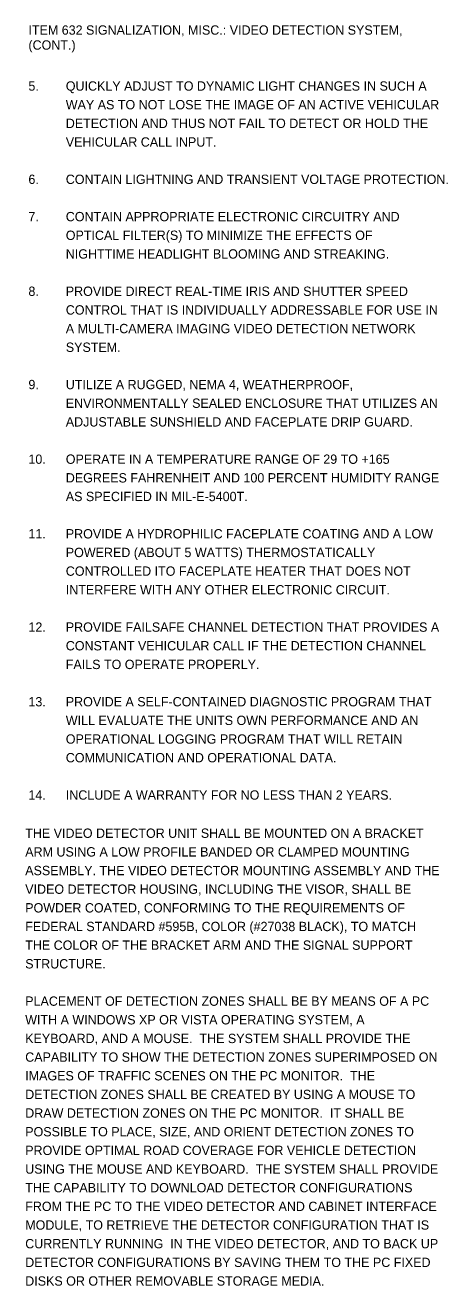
# Model space of a CAD drawing. Extents: x -39 to 75, y -25 to 14.
# Drawn here: x 53.38 to 59.71, y -23.32 to -4.4 of the extents above; entities that cross this region are included whole.
import ezdxf

# ---------------------------------------------------------------- set-up
doc = ezdxf.new("R2010")
doc.units = 0
for name, color, linetype in [('Default', 7, 'Continuous'), ('SH_Data', 7, 'Continuous'), ('SH_Text', 7, 'Continuous')]:
    doc.layers.add(name, color=color, linetype=linetype)

# ---------------------------------------------------------------- blocks, each defined once
blk = doc.blocks.new('POINT_DISPLAY')
at = {"layer": 'Default'}
blk.add_line((0, 0), (0, 0), dxfattribs=at)

msp = doc.modelspace()

# ---------------------------------------------------------------- block references
at = {"layer": 'Default', "xscale": 3.9370000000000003, "yscale": 3.9370000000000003}
msp.add_blockref('POINT_DISPLAY', (53.743, -18.102), dxfattribs=at)

# ---------------------------------------------------------------- texts
at = {"layer": 'SH_Data'}
for s, p in [('ITEM 632 SIGNALIZATION, MISC.: VIDEO DETECTION SYSTEM, ', (53.423, -4.541)), ('(CONT.)', (53.423, -4.766))]:
    msp.add_text(s, height=0.14, rotation=360, dxfattribs=at).set_placement(p)
at = {"layer": 'SH_Text'}
for s, p in [('5.', (53.423, -5.381)), ('QUICKLY ADJUST TO DYNAMIC LIGHT CHANGES IN SUCH A ', (53.983, -5.381)), ('WAY AS TO NOT LOSE THE IMAGE OF AN ACTIVE VEHICULAR ', (53.983, -5.661)), ('DETECTION AND THUS NOT FAIL TO DETECT OR HOLD THE ', (53.983, -5.941)), ('VEHICULAR CALL INPUT.', (53.983, -6.221)), ('6.', (53.423, -6.781)), ('CONTAIN LIGHTNING AND TRANSIENT VOLTAGE PROTECTION.', (53.983, -6.781)), ('7.', (53.423, -7.341)), ('CONTAIN APPROPRIATE ELECTRONIC CIRCUITRY AND ', (53.983, -7.341)), ('OPTICAL FILTER(S) TO MINIMIZE THE EFFECTS OF ', (53.983, -7.621)), ('NIGHTTIME HEADLIGHT BLOOMING AND STREAKING.', (53.983, -7.901)), ('8.', (53.423, -8.461)), ('PROVIDE DIRECT REAL-TIME IRIS AND SHUTTER SPEED ', (53.983, -8.461)), ('CONTROL THAT IS INDIVIDUALLY ADDRESSABLE FOR USE IN ', (53.983, -8.741)), ('A MULTI-CAMERA IMAGING VIDEO DETECTION NETWORK ', (53.983, -9.021)), ('SYSTEM.', (53.983, -9.301)), ('9.', (53.423, -9.861)), ('UTILIZE A RUGGED, NEMA 4, WEATHERPROOF, ', (53.983, -9.861)), ('ENVIRONMENTALLY SEALED ENCLOSURE THAT UTILIZES AN ', (53.983, -10.141)), ('ADJUSTABLE SUNSHIELD AND FACEPLATE DRIP GUARD.', (53.983, -10.421)), ('10.', (53.423, -10.981)), ('OPERATE IN A TEMPERATURE RANGE OF 29 TO +165 ', (53.983, -10.981)), ('DEGREES FAHRENHEIT AND 100 PERCENT HUMIDITY RANGE ', (53.983, -11.261)), ('AS SPECIFIED IN MIL-E-5400T.', (53.983, -11.541)), ('11.', (53.423, -12.101)), ('PROVIDE A HYDROPHILIC FACEPLATE COATING AND A LOW ', (53.983, -12.101)), ('POWERED (ABOUT 5 WATTS) THERMOSTATICALLY ', (53.983, -12.381)), ('CONTROLLED ITO FACEPLATE HEATER THAT DOES NOT ', (53.983, -12.661)), ('INTERFERE WITH ANY OTHER ELECTRONIC CIRCUIT.', (53.983, -12.941)), ('12.', (53.423, -13.501)), ('PROVIDE FAILSAFE CHANNEL DETECTION THAT PROVIDES A ', (53.983, -13.501)), ('CONSTANT VEHICULAR CALL IF THE DETECTION CHANNEL ', (53.983, -13.781)), ('FAILS TO OPERATE PROPERLY.', (53.983, -14.061)), ('13.', (53.423, -14.621)), ('PROVIDE A SELF-CONTAINED DIAGNOSTIC PROGRAM THAT ', (53.983, -14.621)), ('WILL EVALUATE THE UNITS OWN PERFORMANCE AND AN ', (53.983, -14.901)), ('OPERATIONAL LOGGING PROGRAM THAT WILL RETAIN ', (53.983, -15.181)), ('COMMUNICATION AND OPERATIONAL DATA.', (53.983, -15.461)), ('14.', (53.423, -16.021)), ('INCLUDE A WARRANTY FOR NO LESS THAN 2 YEARS.', (53.983, -16.021)), ('THE VIDEO DETECTOR UNIT SHALL BE MOUNTED ON A BRACKET ', (53.375, -16.594)), ('ARM USING A LOW PROFILE BANDED OR CLAMPED MOUNTING ', (53.375, -16.874)), ('ASSEMBLY. THE VIDEO DETECTOR MOUNTING ASSEMBLY AND THE ', (53.375, -17.154)), ('VIDEO DETECTOR HOUSING, INCLUDING THE VISOR, SHALL BE ', (53.375, -17.434)), ('POWDER COATED, CONFORMING TO THE REQUIREMENTS OF ', (53.375, -17.714)), ('FEDERAL STANDARD #595B, COLOR (#27038 BLACK), TO MATCH ', (53.375, -17.994)), ('THE COLOR OF THE BRACKET ARM AND THE SIGNAL SUPPORT ', (53.375, -18.274)), ('STRUCTURE.', (53.375, -18.554)), ('PLACEMENT OF DETECTION ZONES SHALL BE BY MEANS OF A PC ', (53.375, -19.114)), ('WITH A WINDOWS XP OR VISTA OPERATING SYSTEM, A ', (53.375, -19.394)), ('KEYBOARD, AND A MOUSE.  THE SYSTEM SHALL PROVIDE THE ', (53.375, -19.674)), ('CAPABILITY TO SHOW THE DETECTION ZONES SUPERIMPOSED ON ', (53.375, -19.954)), ('IMAGES OF TRAFFIC SCENES ON THE PC MONITOR.  THE ', (53.375, -20.234)), ('DETECTION ZONES SHALL BE CREATED BY USING A MOUSE TO ', (53.375, -20.514)), ('DRAW DETECTION ZONES ON THE PC MONITOR.  IT SHALL BE ', (53.375, -20.794)), ('POSSIBLE TO PLACE, SIZE, AND ORIENT DETECTION ZONES TO ', (53.375, -21.074)), ('PROVIDE OPTIMAL ROAD COVERAGE FOR VEHICLE DETECTION ', (53.375, -21.354)), ('USING THE MOUSE AND KEYBOARD.  THE SYSTEM SHALL PROVIDE ', (53.375, -21.634)), ('THE CAPABILITY TO DOWNLOAD DETECTOR CONFIGURATIONS ', (53.375, -21.914)), ('FROM THE PC TO THE VIDEO DETECTOR AND CABINET INTERFACE ', (53.375, -22.194)), ('MODULE, TO RETRIEVE THE DETECTOR CONFIGURATION THAT IS ', (53.375, -22.474)), ('CURRENTLY RUNNING  IN THE VIDEO DETECTOR, AND TO BACK UP ', (53.375, -22.754)), ('DETECTOR CONFIGURATIONS BY SAVING THEM TO THE PC FIXED ', (53.375, -23.034)), ('DISKS OR OTHER REMOVABLE STORAGE MEDIA. ', (53.375, -23.314))]:
    msp.add_text(s, height=0.14, rotation=360, dxfattribs=at).set_placement(p)

doc.saveas('drawing.dxf')
